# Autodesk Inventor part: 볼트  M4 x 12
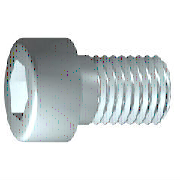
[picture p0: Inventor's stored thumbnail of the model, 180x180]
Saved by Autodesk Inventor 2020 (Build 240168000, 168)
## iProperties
Created: 2015-12
Part Number: 볼트  M4 x 12
Material: 스테인리스강
Description: 6각머리 태핑 나사
Document SubType Name: Modeling
Standard: KS B 1003
Designer: mdu
Standards Organization: KS
Language: ko-KR
Size Designation: M 4 x 12
Categories: <MemberInstance><Categories><Category DisplayName="조임쇠" InternalName="e4da775c-781d-43d5-af7c-5136215cf5a6" Mnemonic="FSTN"><Category DisplayName="볼트" InternalN
Density: 8.08 g/cm^3
Mass: 2.09412 g
Surface Area: 3.0572 cm^2
Volume: 0.259174 cm^3
Appearance: 반광택
IsCustomPart: 0
Author: mdu
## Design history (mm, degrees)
sketch "스케치1"
  geometry: L1 (-1, 0)-(10, 0); L2 (10, 0)-(10, 2); L3 (10, 2)-(1.75, 2); L4 (1.75, 2)-(1.32, 2); L5 (1.32, 2)-(0, 2); L6 (0, 2)-(0, 3.5); L7 (0, 3.5)-(-4, 3.5); L8 (-4, 3.5)-(-4, 1.732); L9 (-4, 1.732)-(-2, 1.732); L10 (-2, 1.732)-(-1, 0); L11 (-7.2, 0)-(15.2, 0) reference; L12 (0, -0.7)-(0, 4.2) reference; L13 (1.75, 2)-(0, 2)
  constraints: 22 end point, 6 parallel, 2 collinear, 2 perpendicular, 1 horizontal, 1 point on line
  dimensions: "d1" = 8.25 distance from line of L3.end L2 (= GEL); "d2" = 0.42952 distance of L4.end L3.end (computed from GAL); "d3" = 4 distance between parallel lines of L8 L6 (= KOH); "d4" = 2 distance of L8.end L9.end (= INTI); "d5" = 60 deg angle of L10 L1; "d6" = 4 diameter of L3 L1 (= GD); "d7" = 4 diameter of L5 L1 (= BDM); "d8" = 3.4641 diameter of L9 L1 (= 1.1547 x SW); "d9" = 7 diameter of L7 L1 (= KOD); "d26" = 10 distance between parallel lines of L12 L2 (= NLG)
revolve "본체" sketch "스케치1" stored, may be unused: angle "d10" = 90 deg
sketch "스케치2"
  geometry: L1 (0, -4.9)-(0, 4.9) reference; L2 (-4.9, 0)-(4.9, 0) reference; L3 (1.732, 0)-(0.866, -1.5); L4 (0.866, -1.5)-(-0.866, -1.5); L5 (-0.866, -1.5)-(-1.732, 0); L6 (-1.732, 0)-(-0.866, 1.5); L7 (-0.866, 1.5)-(0.866, 1.5); L8 (0.866, 1.5)-(1.732, 0); 2 further points
  constraints: 12 end point, 1 coincident, 1 horizontal alignment, 1 point on line, 12 other
extrude "슬롯" join sketch "스케치2" stored distance "d11" = 10; taper "d12" = 0 deg
workplane "Work Plane1"
fillet "Fillet2" dims "d30" = 0.1 (= R)
body "Solid1"
fillet "모깎기1" dims "d17" = 0.4 (= RR)
feature "스레드" dims "d13" = 8.25 (= GEL), "d14" = 0
chamfer "모따기1" distance "d15" = 0.42941 (= -0.5 x SPD + 0.5 x GD); stored, may be unused: second distance "d16" = 0.42941 (= GUL), angle "d27" = 45 deg
other parameters: "GD" = 4 (= NND) [user parameter; used in 2 equation terms], "NLG" = 10 [user parameter; used in 1 equation term], "GEL" = 8.25 [user parameter; used in 2 equation terms], "KOD" = 7 [user parameter; used in 1 equation term], "KOH" = 4 [user parameter; used in 1 equation term], "INTI" = 2 [user parameter; used in 1 equation term], "GAL" = 0.42941 (= 0.61345 x PTC) [user parameter; used in 1 equation term], "GUL" = 0.42941 (= 0.61345 x PTC) [user parameter; used in 1 equation term], "BDM" = 4 (= NND) [user parameter; used in 1 equation term], "SW" = 3 [user parameter; used in 2 equation terms], "RR" = 0.4 [user parameter; used in 1 equation term], "SPD" = 3.14117 (= NND - 1.2269 x PTC) [user parameter; used in 1 equation term], "d19" = 0, "d28" = 0, "d29" = 0, "R" = 0.1 [user parameter; used in 1 equation term], "PHH" = 0.2 [user parameter], "GD1" = 3.14117 (= THREADDIA - 1.2269 x PTC) [user parameter], "THREADDIA" = 4 [user parameter; used in 1 equation term], "FAWI" = 45 deg [user parameter], "TPU" = 14.28571 (computed from PTC) [user parameter], "PTC" = 0.7 [user parameter; used in 5 equation terms], "NND" = 4 [user parameter; used in 3 equation terms], "TOA" = 30 deg [user parameter], "E0" = 3.465 (= 1.155 x SW) [user parameter]
